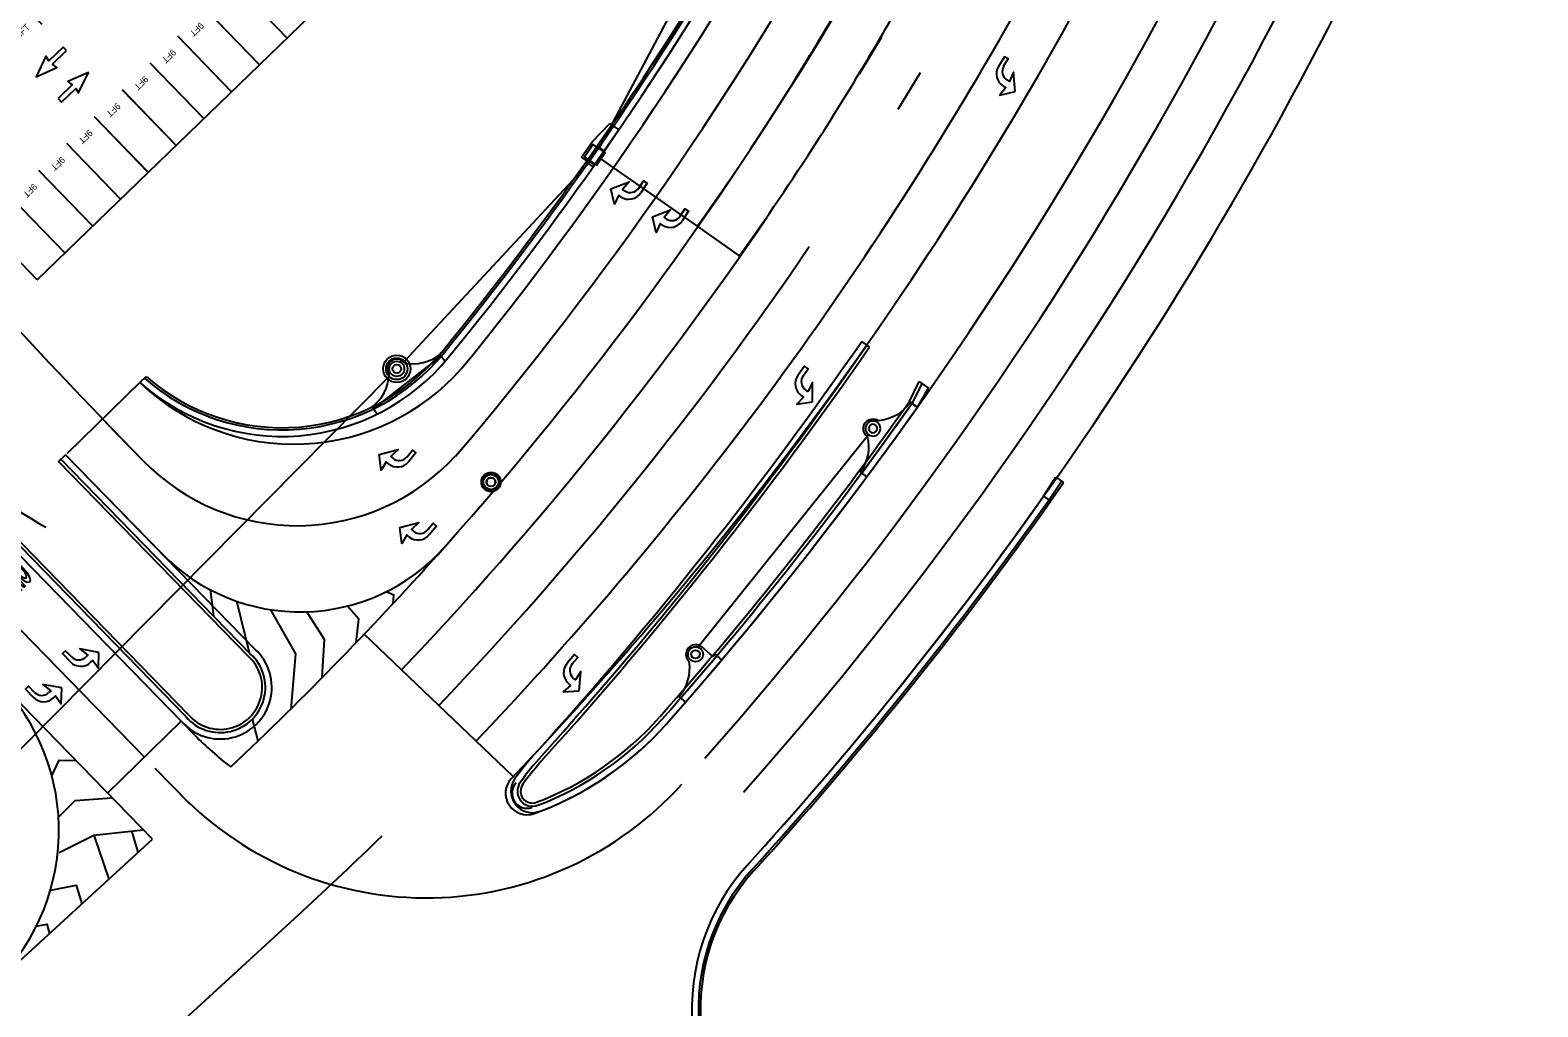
# Model space of a CAD drawing. Extents: x 468143 to 491361, y 1438528 to 1468730.
# Drawn here: x 490836.5 to 491187.7, y 1467623.5 to 1467851.1 of the extents above; entities that cross this region are included whole.
import ezdxf

# ---------------------------------------------------------------- set-up
doc = ezdxf.new("R2010")
doc.units = 0
doc.layers.add('Default', color=7, linetype='Continuous')
doc.layers.add('Xreference_dp', color=7, linetype='Continuous')

# ---------------------------------------------------------------- blocks, each defined once
blk = doc.blocks.new('POINT_DISPLAY')
at = {"layer": 'Default'}
blk.add_line((0, 0), (0, 0), dxfattribs=at)
blk = doc.blocks.new('InltCurb2_35')
at = {"layer": 'Default'}
for p, q in [((-10, 2), (-10, 0)), ((-10, 1.5), (10, 1.5)), ((10, 2), (10, 0))]:
    blk.add_line(p, q, dxfattribs=at)
for radius in [1.75, 1]:
    blk.add_circle((0, 5.5), radius, dxfattribs=at)
for centre, radius, start, end in [((0, 5.5), 2.25, 0, 180), ((-9.85, 12), 10, 269.1432, 319.4677), ((9.85, 12), 10, 220.5323, 270.8568)]:
    blk.add_arc(centre, radius, start, end, dxfattribs=at)
for p in [(-0.66, 7.12), (0, 7.75), (0, 7.25), (0, 7.25), (0.7, 7.1), (-1.75, 5.5), (-1.75, 5.5), (-1.62, 4.84), (-1.6, 6.2), (-1.26, 4.28), (-1.22, 6.76), (-0.7, 3.9), (0, 5.5), (0, 5.5), (0, 3.75), (0, 3.75), (0.66, 3.88), (1.22, 4.24), (1.26, 6.72), (1.6, 4.8), (1.62, 6.16), (1.75, 5.5), (1.75, 5.5), (0, 0), (0, 0)]:
    blk.add_blockref('POINT_DISPLAY', p, dxfattribs=at)
blk = doc.blocks.new('MHCover2')
at = {"layer": 'Default'}
for radius in [2, 1.06, 1]:
    blk.add_circle((0, 0), radius, dxfattribs=at)
for p in [(-2, 0), (-2, 0), (-1.83, 0.81), (-1.39, 1.43), (-0.75, 1.85), (0, 2.5), (0, 2), (0, 2), (0, 0), (0, 0), (0, 0), (0.81, 1.83), (1.43, 1.39), (1.85, 0.75), (2, 0), (2, 0), (-1.85, -0.75), (-1.43, -1.39), (-0.81, -1.83), (0, -2), (0, -2), (0, -2.5), (0.75, -1.85), (1.39, -1.43), (1.83, -0.81)]:
    blk.add_blockref('POINT_DISPLAY', p, dxfattribs=at)
blk = doc.blocks.new('PBottom35Dia')
at = {"layer": 'Default'}
for radius in [2.25, 1.75, 1.75]:
    blk.add_circle((0, 0), radius, dxfattribs=at)
for p in [(-1.75, 0), (-1.75, 0), (-1.6, 0.7), (-1.22, 1.26), (-0.66, 1.62), (0, 1.75), (0, 1.75), (0, 1.75), (0, 0), (0, 0), (0.7, 1.6), (1.26, 1.22), (1.62, 0.66), (1.75, 0), (1.75, 0), (-1.62, -0.66), (-1.26, -1.22), (-0.7, -1.6), (0, -1.75), (0, -1.75), (0, -1.75), (0.66, -1.62), (1.22, -1.26), (1.6, -0.7)]:
    blk.add_blockref('POINT_DISPLAY', p, dxfattribs=at)
blk = doc.blocks.new('InltCurb1_35')
at = {"layer": 'Default'}
for p, q in [((2.25, 2), (2.25, 5.5)), ((-10, 2), (-10, 0)), ((-10, 1.5), (3, 1.5)), ((3, 2), (2.25, 2)), ((3, 0), (3, 2))]:
    blk.add_line(p, q, dxfattribs=at)
for radius in [1.75, 1]:
    blk.add_circle((0, 5.5), radius, dxfattribs=at)
for centre, radius, start, end in [((0, 5.5), 2.25, 0, 180), ((-9.85, 12), 10, 269.1432, 319.4677)]:
    blk.add_arc(centre, radius, start, end, dxfattribs=at)
for p in [(-0.66, 7.12), (0, 7.75), (0, 7.25), (0, 7.25), (0.7, 7.1), (-1.75, 5.5), (-1.75, 5.5), (-1.62, 4.84), (-1.6, 6.2), (-1.26, 4.28), (-1.22, 6.76), (-0.7, 3.9), (0, 5.5), (0, 5.5), (0, 3.75), (0, 3.75), (0.66, 3.88), (1.22, 4.24), (1.26, 6.72), (1.6, 4.8), (1.62, 6.16), (1.75, 5.5), (1.75, 5.5), (0, 0), (0, 0)]:
    blk.add_blockref('POINT_DISPLAY', p, dxfattribs=at)
blk = doc.blocks.new('InltCurb5')
at = {"layer": 'Default'}
for p, q in [((-2.25, 3.5), (-8, 2.5)), ((-8, 2.5), (-8, 0)), ((-8, 1.5), (2.5, 1.5)), ((-8, 0), (2.5, 0)), ((2.25, 3.5), (-2.25, 3.5)), ((-1.96, 0), (-1.96, 1.5)), ((1.95, 0), (1.95, 1.5)), ((2.25, 2), (2.25, 3.5)), ((2.5, 2), (2.25, 2)), ((2.5, 0), (2.5, 2))]:
    blk.add_line(p, q, dxfattribs=at)
blk.add_lwpolyline([(-1.75, -0.5), (1.75, -0.5), (1.75, 3), (-1.75, 3)], close=True, dxfattribs=at)
for p in [(-1.75, 3), (-1.75, 1.25), (-1.75, 1.25), (0, 3.5), (0, 3), (0, 3), (0, 1.25), (0, 1.25), (1.75, 3), (1.75, 1.25), (1.75, 1.25), (-1.75, -0.5), (0, 0), (0, 0), (0, -0.5), (0, -0.5), (1.75, -0.5)]:
    blk.add_blockref('POINT_DISPLAY', p, dxfattribs=at)
blk = doc.blocks.new('JBottom50Dia')
at = {"layer": 'Default'}
for radius in [3.17, 2.5, 2.5]:
    blk.add_circle((0, 0), radius, dxfattribs=at)
for p in [(-2.29, 1.01), (-1.74, 1.79), (-0.94, 2.32), (0, 2.5), (0, 2.5), (0, 2.5), (0, 0), (0, 0), (0, 0), (1.01, 2.29), (1.79, 1.74), (2.32, 0.94), (2.5, 0), (2.5, 0), (-2.5, 0), (-2.5, 0), (-2.32, -0.94), (-1.79, -1.74), (-1.01, -2.29), (0, -2.5), (0, -2.5), (0, -2.5), (0.94, -2.32), (1.74, -1.79), (2.29, -1.01)]:
    blk.add_blockref('POINT_DISPLAY', p, dxfattribs=at)
blk = doc.blocks.new('DALeftTurn_1')
at = {"layer": 'Default'}
for points in [[(5.67, 3.17), (2, 0.5), (4.33, 0.83), (4.33, 0.17)], [(6, 0.17), (6, 0.83), (8.25, 0.5), (5.67, 3.17)], [(2, -2.17), (0, -2.17), (0, -3.17), (2.67, -3.17)]]:
    blk.add_lwpolyline(points, dxfattribs=at)
for centre, radius in [((2, 0.17), 2.33), ((2.67, 0.17), 3.33)]:
    blk.add_arc(centre, radius, 270, 0, dxfattribs=at)
blk = doc.blocks.new('DARightTurn')
at = {"layer": 'Default'}
for points in [[(2, 2.17), (0, 2.17), (0, 3.17), (2.67, 3.17)], [(5.67, -3.17), (2, -0.5), (4.33, -0.83), (4.33, -0.17)], [(6, -0.17), (6, -0.83), (8.25, -0.5), (5.67, -3.17)]]:
    blk.add_lwpolyline(points, dxfattribs=at)
for centre, radius in [((2, -0.17), 2.33), ((2.67, -0.17), 3.33)]:
    blk.add_arc(centre, radius, 360, 90, dxfattribs=at)
blk = doc.blocks.new('ONLY_5')
at = {"layer": 'Default'}
for p, q in [((1.94, 3.96), (6.06, 3.96)), ((5.6, 3.63), (2.4, 3.63)), ((6.06, 1.96), (1.94, 1.96)), ((2.4, 2.29), (5.6, 2.29))]:
    blk.add_line(p, q, dxfattribs=at)
for points in [[(0, -0.12), (0, 0.21), (5, 1.13), (0, 1.13), (0, 1.46), (8, 1.46), (8, 1.13), (2.9, 0.21), (8, 0.21), (8, -0.12), (0, -0.12)], [(1.33, -2.12), (0, -2.12), (0, -0.79), (8, -0.79), (8, -1.12), (1.33, -1.12), (1.33, -2.12)], [(8, -3.96), (3.67, -3.12), (0, -3.12), (0, -2.79), (3.67, -2.79), (8, -1.96), (8, -2.3), (4.57, -2.96), (8, -3.62), (8, -3.96)]]:
    blk.add_lwpolyline(points, dxfattribs=at)
for major_axis, ratio, start_param, end_param in [((4, 0), 0.291667, 2.111896, 4.171289), ((2.67, 0), 0.3125, 2.214297, 4.068888), ((2.67, 0), 0.3125, 5.35589, 7.210481), ((4, 0), 0.291667, 5.253489, 7.312882)]:
    blk.add_ellipse((4, 2.96), major_axis=major_axis, ratio=ratio, start_param=start_param, end_param=end_param, dxfattribs=at)
blk = doc.blocks.new('STALL 9FT SURFACE LOT')
at = {"layer": 'Default'}
for points in [[(0, 0), (0, 216)], [(108, 216), (108, 0)]]:
    blk.add_lwpolyline(points, dxfattribs=at)
blk.add_text('9FT', height=18, dxfattribs=at).set_placement((35.2, 14.1))
blk = doc.blocks.new('arrow-thru')
at = {"layer": 'Default'}
blk.add_lwpolyline([(14.99997, 0), (28.999942, 0), (28.999942, 54.99989), (43.999912, 51.999896), (21.999956, 111.999776), (0, 51.999896), (14.99997, 54.99989)], close=True, dxfattribs=at)

msp = doc.modelspace()

# ---------------------------------------------------------------- linework, layer by layer
at = {"layer": 'Xreference_dp'}
for p, q in [((490838.14, 1467792.91), (490999.83, 1467949.37)), ((490838.14, 1467792.91), (490999.83, 1467949.37)), ((490969.03, 1467823.45), (491035.76, 1467949.31)), ((491029.71, 1467840.92), (491034.87, 1467849.48)), ((491038.73, 1467832.68), (491043.91, 1467841.22)), ((490923.67, 1467773.92), (490967.04, 1467820.57)), ((490969.08, 1467821.29), (490991.85, 1467805.36)), ((490991.85, 1467805.36), (491001.69, 1467798.48)), ((491032.04, 1467777.25), (491030.19, 1467778.54)), ((490818.77, 1467667.92), (490920.14, 1467770.38)), ((490862.05, 1467768.96), (490863.51, 1467770.38)), ((490845.09, 1467752.44), (490862.28, 1467769.19)), ((491041.35, 1467764.55), (491043.59, 1467769.18)), ((491044.2, 1467768.75), (491041.96, 1467764.12)), ((491043.18, 1467763.25), (491045.75, 1467767.67)), ((491043.59, 1467769.18), (491045.75, 1467767.67)), ((491041.35, 1467764.55), (491043.18, 1467763.25)), ((490862.86, 1467750.72), (490853.35, 1467760.49)), ((490862.85, 1467750.72), (490856.49, 1467757.26)), ((490862.85, 1467750.72), (490856.49, 1467757.26)), ((490992.05, 1467707.29), (491031.8, 1467756.82)), ((490843.14, 1467750.55), (490844.75, 1467752.12)), ((490887.34, 1467705.15), (490843.14, 1467750.55)), ((490887.87, 1467705.69), (490843.68, 1467751.07)), ((490888.91, 1467706.77), (490844.75, 1467752.12)), ((490867.16, 1467729.11), (490844.75, 1467752.12)), ((491072.56, 1467742.45), (491075.4, 1467746.93)), ((491073.79, 1467741.58), (491076.77, 1467745.97)), ((491074.2, 1467741.3), (491077.18, 1467745.69)), ((491075.4, 1467746.93), (491077.18, 1467745.69)), ((491072.56, 1467742.45), (491074.2, 1467741.3)), ((490871.72, 1467690.03), (490827.56, 1467735.37)), ((490874.84, 1467686.82), (490827.56, 1467735.37)), ((490872.82, 1467691.04), (490828.63, 1467736.42)), ((490873.37, 1467691.55), (490829.17, 1467736.94)), ((490863.12, 1467681.66), (490818.96, 1467727)), ((490949.05, 1467677.17), (490914.31, 1467710.29)), ((490864.97, 1467662.56), (490829.03, 1467699.46)), ((490854.52, 1467673.28), (490871.72, 1467690.03)), ((490865.57, 1467679.14), (490873.62, 1467670.87)), ((490851.35, 1467663.5), (490862.81, 1467664.77)), ((490827.02, 1467627.73), (490864.97, 1467662.56)), ((490861.63, 1467659.5), (490860.17, 1467664.48)), ((491005.34, 1467658.46), (491003.51, 1467656.43)), ((491006.45, 1467657.46), (491004.62, 1467655.42)), ((491006.82, 1467657.12), (491004.99, 1467655.09)), ((490849.5, 1467599.51), (490899.92, 1467645.77))]:
    msp.add_line(p, q, dxfattribs=at)
for points in [[(490879.3, 1467714.49), (490878.55, 1467720.62)], [(490887.63, 1467705.94), (490884.62, 1467718)], [(490921.03, 1467717.42), (490921.18, 1467719.42), (490919.4, 1467720.19)], [(490897.34, 1467692.88), (490898.41, 1467705.72), (490892.57, 1467716.03)], [(490904.49, 1467700.28), (490905.05, 1467709.07), (490900.93, 1467715.53)], [(490912.46, 1467708.36), (490913.08, 1467713.83), (490910.38, 1467716.9)], [(490889.58, 1467685.45), (490888.29, 1467690.56)], [(490841.56, 1467677.34), (490843.25, 1467680.95), (490847.15, 1467680.86)], [(490843.11, 1467667.71), (490847.03, 1467671.55), (490855.54, 1467672.23)], [(490843.24, 1467659.44), (490851.35, 1467663.5), (490854.86, 1467653.28)], [(490841.29, 1467650.69), (490847.25, 1467651.85), (490848.53, 1467647.48)], [(490837.97, 1467642.3), (490840.39, 1467642.77), (490841.03, 1467640.59)]]:
    msp.add_lwpolyline(points, dxfattribs=at)
for centre, radius, start, end in [((490326.6, 1468270.61), 788.01, 320.77076, 342.66292), ((490326.6, 1468270.61), 800.01, 319.56921, 342.66292), ((490326.6, 1468270.61), 878.01, 318.55019, 342.66952), ((490326.6, 1468270.61), 890.01, 318.55019, 342.66952), ((490326.6, 1468270.61), 902.01, 318.55019, 342.67608), ((490326.6, 1468270.61), 812.01, 318.31329, 339.75439), ((490326.6, 1468270.61), 782.01, 320.77076, 338.48479), ((490326.6, 1468270.61), 782.51, 320.77076, 338.48479), ((490326.6, 1468270.61), 784.01, 320.77076, 338.48479), ((490326.6, 1468270.61), 914.01, 317.78137, 336.51402), ((490326.6, 1468270.61), 860.01, 316.32535, 332.2096), ((490406.06, 1468216.94), 716.13, 327.4546, 331.15974), ((490406.06, 1468216.94), 728.13, 327.4546, 331.15974), ((490326.6, 1468270.61), 848.01, 316.36635, 330.6078), ((490541.01, 1468130.82), 556.04, 324.1752, 327.4546), ((492021.82, 1468883.24), 1620.43, 220.82968, 224.016), ((492021.82, 1468883.24), 1620.43, 220.82968, 224.016), ((490541.01, 1468130.82), 568.04, 324.1752, 327.4546), ((490326.6, 1468270.61), 824.01, 316.36635, 325.79371), ((490326.6, 1468270.61), 836.01, 316.36635, 325.79371), ((490249.01, 1468319.15), 950, 317.95674, 325.31566), ((490249.01, 1468319.15), 951.5, 317.95674, 325.31566), ((490249.01, 1468319.15), 952.25, 317.95674, 325.31566), ((490939.22, 1467908.98), 200, 221.9847, 240.3183), ((490939.22, 1467908.98), 200, 221.9847, 240.3183), ((490895.18, 1467806.4), 50, 228.4973, 320.7708), ((490895.18, 1467806.4), 48.5, 228.6293, 320.7708), ((490895.18, 1467806.4), 47.97, 228.6782, 320.7708), ((490897.94, 1467806.63), 52.04, 226.3803, 318.6538), ((490326.6, 1468270.61), 875.76, 318.56884, 324.70067), ((490326.6, 1468270.61), 876.51, 318.56884, 324.70087), ((490326.6, 1468270.61), 878.01, 318.56884, 324.70067), ((490898.69, 1467785.6), 50, 224.2382, 317.4697), ((490326.6, 1468270.61), 914.01, 317.95297, 324.70067), ((490902.8, 1467771.96), 50, 319.126, 319.1264), ((490326.6, 1468270.61), 915.51, 317.95297, 324.70067), ((490326.6, 1468270.61), 916.01, 317.95297, 324.70067), ((490899.4, 1467760.5), 45, 224.2381, 318.3133), ((490326.6, 1468270.61), 812.01, 313.27448, 318.31329), ((490880.78, 1467697.92), 12.02, 221.0566, 47.4196), ((490880.78, 1467697.92), 10.52, 220.8372, 47.639), ((490880.78, 1467697.92), 9.77, 220.7091, 47.7671), ((490793.21, 1467664.58), 50, 312.5382, 44.2381), ((490928.57, 1467739.14), 75, 289.761, 318.4504), ((490928.57, 1467739.14), 72.75, 290.8559, 318.5914), ((490928.57, 1467739.14), 73.5, 290.8559, 318.6686), ((490928.57, 1467739.14), 75, 290.8559, 318.6686), ((490928.57, 1467739.14), 75, 224.2381, 232.8017), ((491010.21, 1467632.71), 75, 137.9567, 144.1278), ((491010.21, 1467632.71), 73.5, 137.9567, 144.1278), ((491010.21, 1467632.71), 72.75, 137.9567, 144.1278), ((490928.8, 1467728.88), 80, 224.2381, 318.0257), ((490952.24, 1467673.27), 5, 136.3254, 289.761), ((490953.49, 1467673.73), 5, 144.1278, 290.8559), ((490952.24, 1467673.27), 3.5, 136.3254, 289.761), ((490953.49, 1467673.73), 3.5, 144.1278, 290.8559), ((490953.49, 1467673.73), 2.75, 144.1278, 290.8559), ((490326.6, 1468270.61), 848.01, 312.53817, 314.26744), ((491040.64, 1467622.94), 50, 137.953, 231.508), ((491040.64, 1467622.94), 50, 137.953, 231.508), ((491040.64, 1467622.94), 48.5, 137.953, 231.508), ((491040.64, 1467622.94), 48, 137.953, 231.508)]:
    msp.add_arc(centre, radius, start, end, dxfattribs=at)

# ---------------------------------------------------------------- block references
for name, p, xscale, yscale, rotation in [('STALL 9FT SURFACE LOT', (490890.33, 1467868.41), 0.08333072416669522, 0.08333072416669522, -135.9654817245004), ('STALL 9FT SURFACE LOT', (490890.33, 1467868.41), 0.08333072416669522, 0.08333072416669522, -135.9654817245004), ('STALL 9FT SURFACE LOT', (490832.73, 1467846.23), 0.0833307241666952, 0.08333072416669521, 44.05706724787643), ('STALL 9FT SURFACE LOT', (490832.73, 1467846.23), 0.0833307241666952, 0.08333072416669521, 44.05706724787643), ('STALL 9FT SURFACE LOT', (490883.86, 1467862.15), 0.08333072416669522, 0.08333072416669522, -135.9654817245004), ('STALL 9FT SURFACE LOT', (490883.86, 1467862.15), 0.08333072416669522, 0.08333072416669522, -135.9654817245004), ('STALL 9FT SURFACE LOT', (490877.39, 1467855.9), 0.08333072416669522, 0.08333072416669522, -135.9654817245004), ('STALL 9FT SURFACE LOT', (490877.39, 1467855.9), 0.08333072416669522, 0.08333072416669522, -135.9654817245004), ('arrow-thru', (490845.86, 1467845.39), 0.0833307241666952, 0.08333072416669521, 134.05706724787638), ('arrow-thru', (490845.86, 1467845.39), 0.0833307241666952, 0.08333072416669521, 134.05706724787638), ('STALL 9FT SURFACE LOT', (490870.92, 1467849.64), 0.08333072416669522, 0.08333072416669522, -135.9654817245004), ('STALL 9FT SURFACE LOT', (490870.92, 1467849.64), 0.08333072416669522, 0.08333072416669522, -135.9654817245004), ('arrow-thru', (490842.14, 1467836.05), 0.08333072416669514, 0.08333072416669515, -45.942932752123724), ('arrow-thru', (490842.14, 1467836.05), 0.08333072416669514, 0.08333072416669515, -45.942932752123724), ('STALL 9FT SURFACE LOT', (490864.45, 1467843.39), 0.08333072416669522, 0.08333072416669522, -135.9654817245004), ('STALL 9FT SURFACE LOT', (490864.45, 1467843.39), 0.08333072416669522, 0.08333072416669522, -135.9654817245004), ('STALL 9FT SURFACE LOT', (490857.97, 1467837.13), 0.08333072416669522, 0.08333072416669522, -135.9654817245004), ('STALL 9FT SURFACE LOT', (490857.97, 1467837.13), 0.08333072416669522, 0.08333072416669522, -135.9654817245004), ('STALL 9FT SURFACE LOT', (490851.5, 1467830.88), 0.08333072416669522, 0.08333072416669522, -135.9654817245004), ('STALL 9FT SURFACE LOT', (490851.5, 1467830.88), 0.08333072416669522, 0.08333072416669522, -135.9654817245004), ('STALL 9FT SURFACE LOT', (490845.03, 1467824.62), 0.08333072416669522, 0.08333072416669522, -135.9654817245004), ('STALL 9FT SURFACE LOT', (490845.03, 1467824.62), 0.08333072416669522, 0.08333072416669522, -135.9654817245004), ('STALL 9FT SURFACE LOT', (490838.56, 1467818.36), 0.08333072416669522, 0.08333072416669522, -135.9654817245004), ('STALL 9FT SURFACE LOT', (490838.56, 1467818.36), 0.08333072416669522, 0.08333072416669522, -135.9654817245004), ('STALL 9FT SURFACE LOT', (490832.09, 1467812.11), 0.08333072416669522, 0.08333072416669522, -135.9654817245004), ('STALL 9FT SURFACE LOT', (490832.09, 1467812.11), 0.08333072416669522, 0.08333072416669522, -135.9654817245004)]:
    msp.add_blockref(name, p, dxfattribs=dict(at, xscale=xscale, yscale=yscale, rotation=rotation))
for name, p, rotation in [('DALeftTurn_1', (491066.15, 1467843.25), -120.88522870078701), ('DARightTurn', (490977.54, 1467817.14), -123.07198921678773), ('DARightTurn', (490987.21, 1467810.59), -123.07198921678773), ('InltCurb2_35', (490925.27, 1467767.8), 37.729756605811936), ('JBottom50Dia', (490921.9, 1467772.15), 135.0686724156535), ('DALeftTurn_1', (491019.48, 1467770.9), -125.7992134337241), ('DARightTurn', (490923.89, 1467754.56), -129.43527811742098), ('MHCover2', (490943.85, 1467745.77), 128.51033933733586), ('PBottom35Dia', (490943.85, 1467745.77), 128.51033933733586), ('DARightTurn', (490928.69, 1467737.54), -129.43527811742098), ('ONLY_5', (490828.83, 1467726.32), -46.78512691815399), ('DALeftTurn_1', (490846.32, 1467707.98), -46.1637972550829), ('InltCurb1_35', (490995.66, 1467702.05), 49.31615845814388), ('DALeftTurn_1', (490965.72, 1467703.47), -131.1166159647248), ('DALeftTurn_1', (490837.69, 1467699.71), -46.1637972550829)]:
    msp.add_blockref(name, p, dxfattribs=dict(at, rotation=rotation))
for name, p, yscale, rotation in [('InltCurb5', (490969.06, 1467821.3), -0.9999999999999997, -124.71171115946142), ('InltCurb2_35', (491037.29, 1467755.03), -1.0000000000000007, -125.63230583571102)]:
    msp.add_blockref(name, p, dxfattribs=dict(at, yscale=yscale, rotation=rotation))
msp.add_blockref('POINT_DISPLAY', (491005.34, 1467658.46), dxfattribs=at)

doc.saveas('drawing.dxf')
